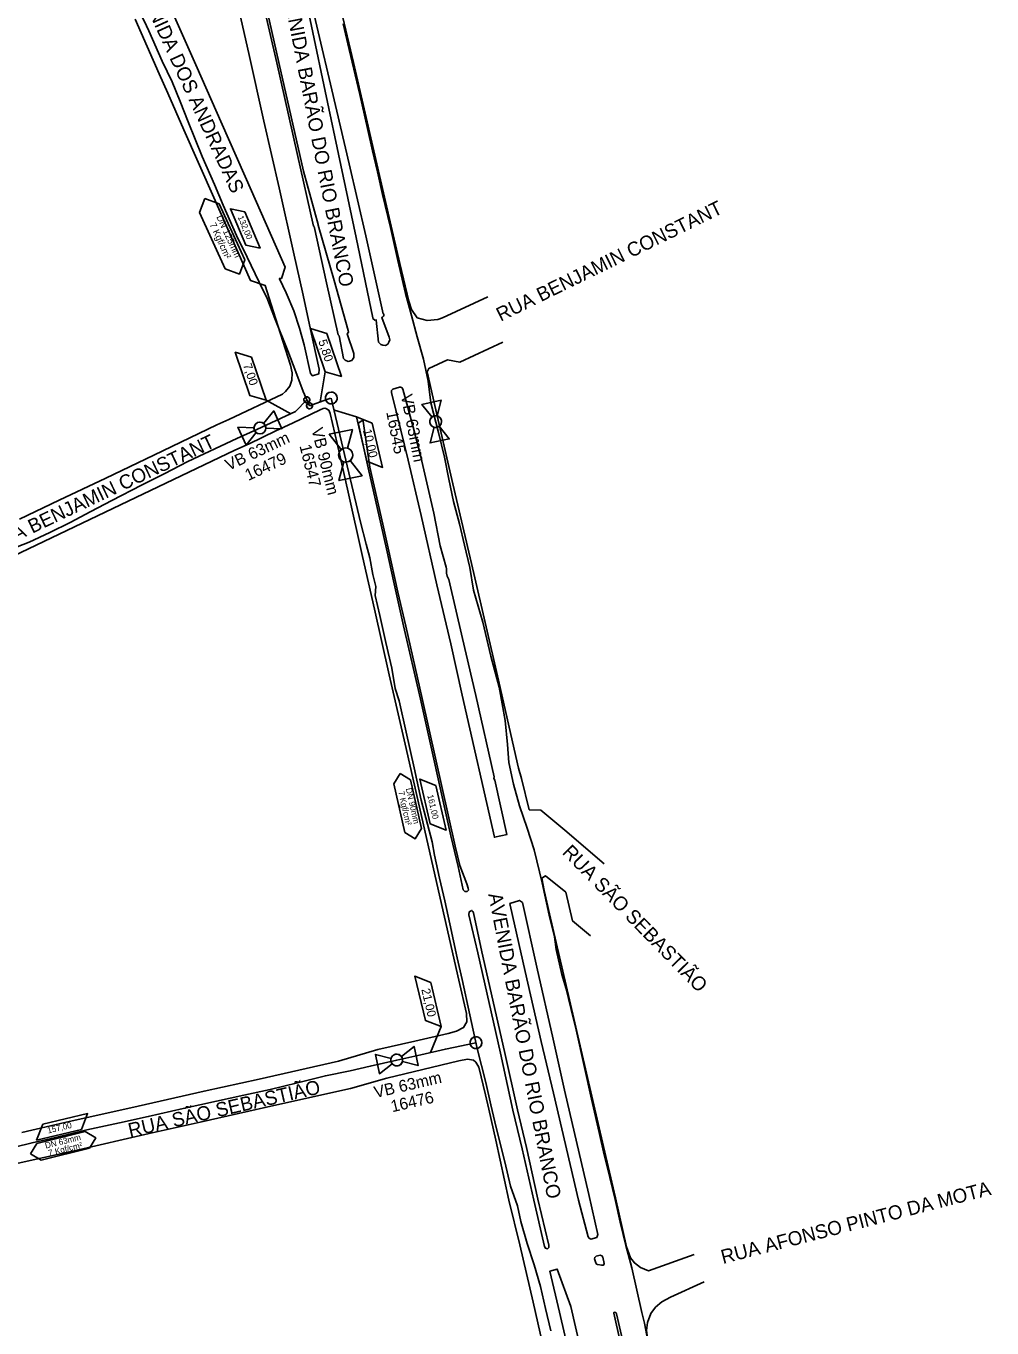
# Model space of a CAD drawing. Extents: x 656692 to 673945, y 7585994 to 7599066.
# Drawn here: x 669731 to 670226, y 7594792 to 7595459 of the extents above; entities that cross this region are included whole.
import ezdxf

# ---------------------------------------------------------------- set-up
doc = ezdxf.new("R2010")
doc.units = 0
for name, color, linetype in [('LOGRADOURO', 7, 'Continuous'), ('LOGRADOURO_TEXTO', 7, 'Continuous'), ('MEIO FIO', 7, 'Continuous'), ('SIMBOLO', 7, 'Continuous'), ('TEXTO', 7, 'Continuous'), ('TUBO_PEAD_GN_125', 7, 'Continuous'), ('TUBO_PEAD_GN_63', 7, 'Continuous'), ('TUBO_PEAD_GN_90', 7, 'Continuous'), ('VALVULA_PEAD_63', 7, 'Continuous'), ('VALVULA_PEAD_90', 7, 'Continuous')]:
    doc.layers.add(name, color=color, linetype=linetype)

# ---------------------------------------------------------------- blocks, each defined once
blk = doc.blocks.new('VALVULA_PEAD_DN_16')
at = {"layer": 'VALVULA_PEAD_63'}
for points in [[(-0.0374, 0.0187), (-0.1395, 0.0698), (-0.1395, -0.0698), (-0.0374, -0.0187)], [(-0.0374, -0.0187), (-0.1395, -0.0698), (-0.1395, 0.0698), (-0.0374, 0.0187)], [(0.0374, -0.0187), (0.1395, -0.0698), (0.1395, 0.0698), (0.0374, 0.0187)], [(0.0374, -0.0187), (0.1395, -0.0698), (0.1395, 0.0698), (0.0374, 0.0187)]]:
    blk.add_lwpolyline(points, dxfattribs=at)
blk.add_circle((0, 0), 0.0419, dxfattribs=at)
for start, end in [(90, 270), (153.43495, 206.56505), (270, 90), (333.43495, 26.56505)]:
    blk.add_arc((0, 0), 0.0419, start, end, dxfattribs=at)
blk = doc.blocks.new('INTERLIGACAO_9')
at = {"layer": 'SIMBOLO'}
blk.add_circle((0, 0), 4.19, dxfattribs=at)
for start, end in [(0, 180), (180, 0)]:
    blk.add_arc((0, 0), 4.19, start, end, dxfattribs=at)
blk = doc.blocks.new('VALVULA_PEAD_DN_17')
for points in [[(-0.0374, 0.0187), (-0.1395, 0.0698), (-0.1395, -0.0698), (-0.0374, -0.0187)], [(-0.0374, -0.0187), (-0.1395, -0.0698), (-0.1395, 0.0698), (-0.0374, 0.0187)], [(0.0374, -0.0187), (0.1395, -0.0698), (0.1395, 0.0698), (0.0374, 0.0187)], [(0.0374, -0.0187), (0.1395, -0.0698), (0.1395, 0.0698), (0.0374, 0.0187)]]:
    blk.add_lwpolyline(points)
blk.add_circle((0, 0), 0.0419)
for start, end in [(90, 270), (153.43495, 206.56505), (270, 90), (333.43495, 26.56505)]:
    blk.add_arc((0, 0), 0.0419, start, end)

msp = doc.modelspace()

# ---------------------------------------------------------------- linework, layer by layer
at = {"layer": 'LOGRADOURO'}
for points in [[(669907.78, 7595565.23), (669885.57, 7595555.02), (669882.73, 7595552.97), (669879.76, 7595549.96), (669876.58, 7595543.18), (669876.74, 7595537.65), (669880.81, 7595518.96), (669884, 7595505.49), (669890.56, 7595477.33), (669899.18, 7595440.34), (669919.49, 7595352.19), (669922.93, 7595337.43), (669927.48, 7595318.19), (669928.82, 7595313.85), (669931.88, 7595309.53), (669937, 7595308.26), (669942.3, 7595308.75), (669944.73, 7595309.52), (669968, 7595320.27)], [(669847.68, 7595493.52), (669859.85, 7595440.29), (669870.31, 7595393.79), (669878.66, 7595356.6), (669879.02, 7595356.35), (669885.28, 7595327.51), (669891.37, 7595300.95), (669891.81, 7595300.34), (669894.13, 7595288.83), (669894.93, 7595287.84), (669896.37, 7595287.28), (669898.32, 7595287.69), (669899.4, 7595289.2), (669899.29, 7595291.4), (669895.9, 7595301.41), (669896.62, 7595302.19), (669896.46, 7595303.07), (669889.34, 7595328.64), (669881.04, 7595356.99), (669881.13, 7595357.44), (669873.53, 7595384.69), (669860.86, 7595440.34), (669848.96, 7595493.48)], [(669874.02, 7595485.91), (669888.13, 7595426.35), (669896.89, 7595388.51), (669905.46, 7595351.58), (669914.41, 7595311.64), (669914.67, 7595311.71), (669914.75, 7595311.59), (669914.73, 7595310.84), (669914.47, 7595310.41), (669914, 7595309.87), (669913.69, 7595309.76), (669917.42, 7595299.72), (669917.73, 7595298.32), (669917.35, 7595297.05), (669916.69, 7595296.08), (669915.57, 7595295.48), (669914.25, 7595295.52), (669913.14, 7595295.97), (669911.95, 7595297.19), (669910.86, 7595308.45), (669910.77, 7595308.49), (669910.17, 7595308.45), (669909.17, 7595309.29), (669909.13, 7595309.57), (669900.55, 7595350.71), (669892.72, 7595387.8), (669884.68, 7595425.72), (669871.99, 7595485.94)], [(669803.34, 7595473.27), (669818.44, 7595439.25), (669832, 7595408.67), (669846.87, 7595374.72), (669864.18, 7595335.47), (669862.28, 7595329.75), (669862.19, 7595329.72), (669861.18, 7595329.67), (669861.26, 7595329.63), (669864.66, 7595322.41), (669868.66, 7595313.11), (669871.61, 7595304.38), (669873.86, 7595295.78), (669877.21, 7595281.13), (669878.24, 7595279.88), (669881.41, 7595280.9), (669881.64, 7595283.26), (669878.48, 7595297.33), (669873.12, 7595322.69), (669868.71, 7595341.65), (669861.05, 7595376.23), (669853.33, 7595410.35), (669845.58, 7595445.09), (669838.19, 7595477.44)], [(669787.41, 7595462.62), (669799.64, 7595434.65), (669804.01, 7595424.72), (669812.31, 7595405.97), (669827.73, 7595371.32), (669846.4, 7595328.72), (669853.89, 7595326.19), (669859.26, 7595309.49), (669866.88, 7595285.36), (669867.82, 7595281.5), (669867.55, 7595277.68), (669866.64, 7595274.59), (669864.44, 7595271.81), (669862.78, 7595270.56), (669835.34, 7595257.59), (669829.11, 7595254.72), (669796.87, 7595239.31), (669772.3, 7595227.42), (669748.41, 7595216.11), (669728.17, 7595206.43)], [(669975.6, 7595297.17), (669953.72, 7595286.93), (669947.3, 7595288.11), (669937.72, 7595283.64), (669936.89, 7595282), (669936.89, 7595281.9), (669942.98, 7595254.99), (669950.14, 7595224.52), (669960.8, 7595178.58), (669972.95, 7595126.26), (669983.77, 7595078.9), (669985.2, 7595073.62), (669989.19, 7595057.63), (669995.12, 7595057.44), (670007.36, 7595047.07), (670027.52, 7595029.85)], [(669729.3, 7594892.29), (669751.27, 7594897.29), (669788.86, 7594905.75), (669822.66, 7594913.51), (669850.87, 7594919.61), (669891.52, 7594928.79), (669911.64, 7594934.74), (669930.59, 7594939.03), (669947.69, 7594943.04), (669951.87, 7594944.08), (669955.55, 7594945.98), (669957.29, 7594948.91), (669956.99, 7594953.18), (669953.17, 7594970.37), (669945.84, 7595002.53), (669935.85, 7595046.14), (669926.24, 7595088.99), (669917.53, 7595126.77), (669910.01, 7595160.43), (669903.81, 7595187.34), (669896.39, 7595220.22), (669890.75, 7595245.28), (669887.26, 7595260.64), (669886.5, 7595262.29), (669885.04, 7595263.21), (669884.55, 7595263.36), (669883.63, 7595263.17), (669882.15, 7595262.52), (669867.9, 7595255.65), (669859.32, 7595251.64), (669845.7, 7595244.97), (669838.43, 7595241.73), (669654.33, 7595153.92)], [(670073.62, 7594829.74), (670050.37, 7594821.42), (670046.23, 7594823.01), (670043.09, 7594825.42), (670041.02, 7594827.99), (670039.06, 7594833.65), (670033.3, 7594858.86), (670027.19, 7594885.07), (670009.76, 7594960.24), (669999.64, 7595004.33), (669996.91, 7595016.3), (669995.63, 7595022.47), (669997.51, 7595023.7), (670007.97, 7595015.36)], [(670007.97, 7595015.36), (670011.36, 7595000.68), (670020.5, 7594993.02)], [(670009.62, 7594778.82), (670004.65, 7594800.2), (669999.77, 7594821.17), (670003.56, 7594822.27), (670010.54, 7594803.15), (670015.84, 7594779.99)], [(670078.86, 7594815.72), (670061.63, 7594807.82), (670057.06, 7594805.5), (670053.89, 7594802.78), (670051.56, 7594799.51), (670049.75, 7594794.84), (670049.27, 7594790.89), (670049.85, 7594786.85), (670054.48, 7594766.8), (670089.15, 7594616.81), (670129.02, 7594627.13)]]:
    msp.add_lwpolyline(points, dxfattribs=at)
for points in [[(669933.72, 7595238.39), (669940.38, 7595209.47), (669943.57, 7595192.8), (669946.66, 7595181.9), (669946.77, 7595180.96), (669946.87, 7595179.87), (669946.76, 7595178.72), (669947.22, 7595177.33), (669948.06, 7595175.5), (669955.08, 7595145.35), (669961.87, 7595116.19), (669971.27, 7595074.5), (669971.09, 7595073.6), (669971.51, 7595072.7), (669977.73, 7595044.96), (669977.83, 7595044.96), (669971.34, 7595043.54), (669971.44, 7595043.54), (669954.91, 7595116.22), (669948.97, 7595142.53), (669941.86, 7595172.76), (669933.77, 7595208.33), (669927.12, 7595236.73), (669923.41, 7595252), (669918.58, 7595271.41), (669918.69, 7595272.32), (669919.27, 7595273.02), (669922.78, 7595274), (669923.33, 7595274.09), (669923.94, 7595273.86), (669924.52, 7595273.13), (669929.68, 7595253.57)], [(669901.92, 7595255.89), (669903.6, 7595257.05), (669904, 7595257), (669904.21, 7595256.72), (669907.61, 7595233.05), (669914.25, 7595203.86), (669916.9, 7595191.64), (669921.97, 7595169.04), (669925.92, 7595151.63), (669934.31, 7595114.51), (669951.32, 7595039), (669953.65, 7595029.09), (669957.3, 7595019.71), (669957.99, 7595017.44), (669958.08, 7595016.39), (669957.35, 7595015.74), (669956.22, 7595015.7), (669955.42, 7595016.56), (669952.77, 7595028.56), (669949.12, 7595044.28), (669933.44, 7595114.16), (669924.86, 7595151.76), (669920.03, 7595173.36), (669916.08, 7595191.21), (669913.31, 7595203.39), (669906.66, 7595232.68), (669901.69, 7595255.2), (669901.59, 7595255.62)], [(669958.36, 7595005.34), (669958.26, 7595003.7), (669962.82, 7594984.29), (669974.41, 7594932.89), (669980.84, 7594903.75), (669985.54, 7594883.92), (669991.59, 7594857.56), (669997.01, 7594833.82), (669997.48, 7594832.96), (669998.51, 7594832.71), (669999.25, 7594833.36), (669999.21, 7594834.46), (669993.66, 7594858.08), (669987.83, 7594884.51), (669983.26, 7594903.9), (669976.48, 7594933.74), (669964.97, 7594984.87), (669960.71, 7595004.71), (669960.27, 7595005.54), (669959.82, 7595006.01)], [(669979.32, 7595009.64), (669979.4, 7595008.76), (669987.12, 7594974.66), (669995.38, 7594938.88), (670001.59, 7594912.33), (670014.47, 7594857.62), (670019.46, 7594838.79), (670019.91, 7594838.08), (670020.68, 7594837.69), (670023.75, 7594838.47), (670024.32, 7594840.05), (670019.71, 7594860.57), (670007.22, 7594913.86), (670001.46, 7594940.06), (669993.17, 7594976.87), (669985.73, 7595010.07), (669984.21, 7595011.18)], [(670023.52, 7594828.95), (670022.76, 7594828.23), (670022.63, 7594827.57), (670023.25, 7594825.5), (670023.62, 7594824.87), (670024.13, 7594824.61), (670026.36, 7594824.23), (670027.28, 7594824.37), (670027.61, 7594825.14), (670026.98, 7594828.36), (670026.45, 7594829.06), (670025.47, 7594829.36)], [(670032.65, 7594800.24), (670033.53, 7594800.1), (670033.87, 7594799.41), (670040.42, 7594771.17), (670058.47, 7594692.58), (670065.55, 7594662.9), (670068.13, 7594650.58), (670068.01, 7594649.64), (670067.16, 7594648.87), (670065.59, 7594648.65), (670064.86, 7594648.74), (670064.35, 7594649.8), (670063.84, 7594662.49), (670055.57, 7594698.95), (670046.47, 7594738.46), (670039.06, 7594770.75), (670032.48, 7594799.71)]]:
    msp.add_lwpolyline(points, close=True, dxfattribs=at)
at = {"layer": 'MEIO FIO'}
for p, q in [((669916.26, 7594920.13), (669953.11, 7594928.98)), ((669953.11, 7594928.98), (669957.58, 7594929.79)), ((669953.11, 7594928.98), (669953.11, 7594928.98)), ((669957.58, 7594929.79), (669960.59, 7594929.39)), ((669957.58, 7594929.79), (669957.58, 7594929.79)), ((669960.59, 7594929.39), (669961.83, 7594928.31)), ((669960.59, 7594929.39), (669960.59, 7594929.39)), ((669961.83, 7594928.31), (669963.38, 7594925.8)), ((669961.83, 7594928.31), (669961.83, 7594928.31)), ((669963.38, 7594925.8), (669966.84, 7594911.47)), ((669963.38, 7594925.8), (669963.38, 7594925.8)), ((669897.69, 7594914.84), (669916.26, 7594920.13)), ((669916.26, 7594920.13), (669916.26, 7594920.13)), ((669859.87, 7594906.42), (669897.69, 7594914.84)), ((669897.69, 7594914.84), (669897.69, 7594914.84)), ((669820.7, 7594897.55), (669859.87, 7594906.42)), ((669859.87, 7594906.42), (669859.87, 7594906.42)), ((669966.84, 7594911.47), (669968.53, 7594904.18)), ((669966.84, 7594911.47), (669966.84, 7594911.47)), ((669968.53, 7594904.18), (669972.14, 7594888.38)), ((669968.53, 7594904.18), (669968.53, 7594904.18)), ((669794.49, 7594891.66), (669820.7, 7594897.55)), ((669820.7, 7594897.55), (669820.7, 7594897.55)), ((669756.06, 7594882.89), (669794.49, 7594891.66)), ((669794.49, 7594891.66), (669794.49, 7594891.66)), ((669972.14, 7594888.38), (669978.82, 7594857.66)), ((669972.14, 7594888.38), (669972.14, 7594888.38)), ((669731.96, 7594877.52), (669756.06, 7594882.89)), ((669756.06, 7594882.89), (669756.06, 7594882.89)), ((669723.65, 7594875.61), (669731.96, 7594877.52)), ((669731.96, 7594877.52), (669731.96, 7594877.52)), ((669978.82, 7594857.66), (669984.35, 7594834.71)), ((669978.82, 7594857.66), (669978.82, 7594857.66)), ((669984.35, 7594834.71), (669991.2, 7594805.3)), ((669984.35, 7594834.71), (669984.35, 7594834.71)), ((669991.2, 7594805.3), (669997.16, 7594778.82)), ((669991.2, 7594805.3), (669991.2, 7594805.3))]:
    msp.add_line(p, q, dxfattribs=at)
at = {"layer": 'SIMBOLO'}
for points in [[(669823.04, 7595370.78), (669830.31, 7595368.08), (669843.47, 7595339.3), (669840.77, 7595332.03), (669833.5, 7595334.74), (669820.34, 7595363.52), (669823.04, 7595370.78)], [(669923.13, 7595076.18), (669928.43, 7595072.85), (669934.07, 7595047.94), (669930.74, 7595042.65), (669925.44, 7595045.99), (669919.8, 7595070.89), (669923.13, 7595076.18)], [(669733.79, 7594881.25), (669737.02, 7594886.6), (669761.81, 7594892.74), (669767.17, 7594889.51), (669763.93, 7594884.15), (669739.15, 7594878.02), (669733.79, 7594881.25)]]:
    msp.add_lwpolyline(points, dxfattribs=at)
at = {"layer": 'TEXTO'}
for p, q in [((669884.63, 7595281.96), (669882.08, 7595266.48)), ((669854.41, 7595267.47), (669867.12, 7595260.45)), ((669900.7, 7595258.88), (669889.4, 7595262.28)), ((669944.05, 7594946.5), (669938.62, 7594933.21))]:
    msp.add_line(p, q, dxfattribs=at)
for points in [[(669843.51, 7595363.89), (669851.31, 7595345.37), (669843.97, 7595346.86), (669836.12, 7595365.5), (669843.51, 7595363.89)], [(669885.56, 7595301.63), (669892.97, 7595279.61), (669884.63, 7595281.96), (669877.18, 7595304.11), (669885.56, 7595301.63)], [(669847.02, 7595289.44), (669854.43, 7595267.43), (669846.09, 7595269.78), (669838.64, 7595291.93), (669847.02, 7595289.44)], [(669847.02, 7595289.44), (669854.43, 7595267.43), (669846.1, 7595269.78), (669838.64, 7595291.93), (669847.02, 7595289.44)], [(669908.81, 7595255.62), (669914.11, 7595233), (669906.04, 7595236.13), (669900.7, 7595258.88), (669908.81, 7595255.62)], [(669941.34, 7595070.03), (669946.7, 7595047.14), (669938.53, 7595050.31), (669933.13, 7595073.33), (669941.34, 7595070.03)], [(669938.75, 7594969.11), (669944.05, 7594946.5), (669935.98, 7594949.63), (669930.64, 7594972.38), (669938.75, 7594969.11)], [(669938.75, 7594969.11), (669944.05, 7594946.5), (669935.98, 7594949.62), (669930.64, 7594972.38), (669938.75, 7594969.11)], [(669740.13, 7594896.55), (669763, 7594901.96), (669759.86, 7594893.79), (669736.84, 7594888.34), (669740.13, 7594896.55)], [(669740.13, 7594896.55), (669763, 7594901.97), (669759.86, 7594893.79), (669736.85, 7594888.34), (669740.13, 7594896.55)]]:
    msp.add_lwpolyline(points, dxfattribs=at)
at = {"layer": 'TUBO_PEAD_GN_125'}
msp.add_line((669887.47, 7595268.4), (669876.69, 7595264.55), dxfattribs=at)
msp.add_lwpolyline([(669772.18, 7595503.71), (669779.22, 7595488.18), (669784.3, 7595477.64), (669786.74, 7595472.07), (669792.04, 7595461.75), (669794.34, 7595456.68), (669801.22, 7595441.08), (669806.29, 7595430.51), (669810.45, 7595420.39), (669814.54, 7595410.08), (669821.65, 7595392.3), (669828.01, 7595377.85), (669832.38, 7595367.25), (669839.26, 7595351.8), (669844.71, 7595340.75), (669852.94, 7595323.62), (669854.78, 7595319.98), (669858.93, 7595309.26), (669865.49, 7595292.74), (669869.6, 7595281.87), (669873.37, 7595271.9), (669876.69, 7595264.55)], dxfattribs=at)
at = {"layer": 'TUBO_PEAD_GN_63'}
for points in [[(669893.91, 7595460.26), (669896.29, 7595449.98), (669898.49, 7595440.62), (669902.38, 7595424.07), (669906.4, 7595406.66), (669908.98, 7595395.07), (669911.46, 7595384.39), (669914.1, 7595372.85), (669918.06, 7595355.89), (669921.92, 7595339), (669925.9, 7595322.07), (669928.85, 7595310.84), (669931.88, 7595299.8), (669935.05, 7595288.36), (669937.37, 7595277.18), (669938.72, 7595265.99), (669942.74, 7595250.85), (669945.83, 7595238.16), (669948.1, 7595226.94), (669950.4, 7595215.45), (669953.51, 7595204.14), (669956.06, 7595193.11), (669958.8, 7595181.77), (669960.6, 7595170.04), (669965.42, 7595153.65), (669969.48, 7595136.31), (669973.72, 7595120.33), (669976.86, 7595103.31), (669978.14, 7595091.07), (669978.79, 7595081.78), (669981.09, 7595070.62), (669984.17, 7595059.54), (669988.21, 7595048.09), (669991.64, 7595037.09), (669995.8, 7595020.1), (669999.42, 7595003.58), (670002.1, 7594992.41), (670003.05, 7594985.92), (670005.96, 7594973.2), (670008.1, 7594965.89), (670011.92, 7594950.26), (670013.25, 7594944.8), (670017.21, 7594927.08), (670021.16, 7594909.32), (670024.99, 7594892.3), (670027.62, 7594880.86), (670030.43, 7594869.23), (670033.18, 7594857.86), (670035.71, 7594846.23), (670038.61, 7594834.33), (670041.67, 7594822.93), (670044.27, 7594811.56), (670046.81, 7594800.06), (670048.31, 7594794.53), (670050.44, 7594782.77)], [(669651.19, 7595156.38), (669652.77, 7595157.35), (669662.73, 7595163.12), (669673.73, 7595168.87), (669684.25, 7595174.12), (669694.82, 7595178.96), (669705.67, 7595183.31), (669715.82, 7595188.05), (669733.03, 7595194.66), (669743.71, 7595199.55), (669754.07, 7595204.78), (669764.71, 7595210.45), (669775.42, 7595215.98), (669790.56, 7595223.91), (669802.13, 7595229.73), (669814.3, 7595236.08), (669839.51, 7595247.78), (669849.68, 7595252.43), (669869.56, 7595261.57), (669875.3, 7595267.62)], [(669715.23, 7594883.17), (669717.75, 7594884.68), (669725.53, 7594884.79), (669734.55, 7594887.01), (669742.89, 7594888.83), (669753.52, 7594891.42), (669762.6, 7594893.55), (669779.39, 7594897.23), (669794.07, 7594900.43), (669811.9, 7594904.5), (669829.06, 7594908.31), (669843.07, 7594911.41), (669856.57, 7594914.29), (669870.57, 7594917.76), (669884.79, 7594921.32), (669897.47, 7594923.92), (669907.73, 7594926.18), (669921.38, 7594929.39), (669933.64, 7594932.07), (669946.24, 7594934.98), (669961.89, 7594938.24)]]:
    msp.add_lwpolyline(points, dxfattribs=at)
at = {"layer": 'TUBO_PEAD_GN_90'}
msp.add_lwpolyline([(669887.8, 7595268.52), (669902.85, 7595204.85), (669905.62, 7595193.6), (669907.56, 7595186.59), (669909.08, 7595178.19), (669910.54, 7595171.99), (669910.33, 7595167.42), (669912.72, 7595157.08), (669915.72, 7595143.27), (669918.75, 7595130.16), (669920.57, 7595119.7), (669922.54, 7595113.43), (669926.11, 7595097.38), (669930.2, 7595079.04), (669933.9, 7595062.49), (669939.45, 7595041.2), (669940.7, 7595034.38), (669943.18, 7595022.57), (669945.93, 7595010.96), (669948.45, 7594999.16), (669952.37, 7594981.66), (669954.81, 7594970.61), (669958.72, 7594952.6), (669962.54, 7594935.27), (669967.02, 7594917.87), (669969.6, 7594906.41), (669972.33, 7594894.79), (669976.69, 7594877.28), (669979.58, 7594864.68), (669983.19, 7594854.63), (669984.87, 7594846.61), (669988.17, 7594835.43), (669991.8, 7594824.45), (669994.95, 7594813.41), (669997.59, 7594802.1), (670000.25, 7594790.64)], dxfattribs=at)

# ---------------------------------------------------------------- block references
at = {"layer": 'SIMBOLO', "rotation": 166.312122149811}
for p, xscale, yscale in [((669887.8, 7595268.52), 0.7229249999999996, 0.7229249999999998), ((669875.28, 7595267.6), 0.3614624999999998, 0.3614624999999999), ((669876.66, 7595264.52), 0.3614624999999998, 0.3614624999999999), ((669961.89, 7594938.24), 0.7229249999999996, 0.7229249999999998)]:
    msp.add_blockref('INTERLIGACAO_9', p, dxfattribs=dict(at, xscale=xscale, yscale=yscale))
at = {"layer": 'VALVULA_PEAD_63'}
for p, xscale, yscale, rotation in [((669941.26, 7595256.44), 72.29249999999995, 72.29249999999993, -78.18143432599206), ((669851.25, 7595253.15), 72.29249999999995, 72.29249999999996, 24.566402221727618), ((669921.34, 7594929.38), 72.2924999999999, 72.29249999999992, 11.818565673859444), ((669921.34, 7594929.38), 72.2924999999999, 72.29249999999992, 11.818565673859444), ((669921.34, 7594929.38), 72.2924999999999, 72.29249999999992, 11.818565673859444)]:
    msp.add_blockref('VALVULA_PEAD_DN_16', p, dxfattribs=dict(at, xscale=xscale, yscale=yscale, rotation=rotation))
at = {"layer": 'VALVULA_PEAD_90', "xscale": 86.75099999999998, "yscale": 86.75099999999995, "rotation": -78.25260528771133}
msp.add_blockref('VALVULA_PEAD_DN_17', (669895.19, 7595239.3), dxfattribs=at)

# ---------------------------------------------------------------- texts
for s, rotation, p in [('VB 63mm', 281.04801, (669923.41, 7595269.85)), ('16545', 281.04801, (669915.92, 7595261.32)), ('VB 90mm', 284.09848, (669877.57, 7595252.5)), ('VB 63mm', 25.04801, (669835.21, 7595231.17)), ('16479', 25.04801, (669845.3, 7595225.97)), ('16547', 284.09848, (669871.46, 7595244.01)), ('VB 63mm', 13.04801, (669910.48, 7594909.85)), ('16476', 13.04801, (669919.04, 7594902.6))]:
    msp.add_text(s, height=6, rotation=rotation).set_placement(p)
at = {"layer": 'LOGRADOURO_TEXTO'}
for s, rotation, p in [('AVENIDA DOS ANDRADAS', 294.63296, (669786.08, 7595483.65)), ('AVENIDA BARÃO DO RIO BRANCO', 280.99349, (669861.99, 7595481.46)), ('RUA BENJAMIN CONSTANT', 26.05221, (669974.54, 7595307.55)), ('RUA BENJAMIN CONSTANT', 25.36438, (669713.85, 7595189.13)), ('RUA SÃO SEBASTIÃO', 314.39127, (670005.68, 7595035.38)), ('AVENIDA BARÃO DO RIO BRANCO', 280.99349, (669968.17, 7595014.31)), ('RUA SÃO SEBASTIÃO', 12.95403, (669784.68, 7594889.75)), ('RUA AFONSO PINTO DA MOTA', 14.4566, (670088.44, 7594824.89))]:
    msp.add_text(s, height=7.2, rotation=rotation, dxfattribs=at).set_placement(p)
at = {"layer": 'TEXTO'}
for s, height, rotation, p in [('7 Kgf/cm²', 3.459, 294.57428, (669825.37, 7595357.4)), ('DN 125mm', 3.459, 294.57428, (669828.86, 7595361.29)), ('132,00', 3.113, 292.84821, (669839.8, 7595361.18)), ('5,80', 4.447, 288.6074, (669881.07, 7595297.65)), ('7,00', 4.447, 288.6074, (669842.53, 7595285.46)), ('10,00', 4.447, 283.19761, (669903.96, 7595252.08)), ('7 Kgf/cm²', 3.113, 282.77499, (669922.06, 7595066.78)), ('DN 90mm', 3.113, 282.77499, (669925.93, 7595068.4)), ('161,00', 3.113, 283.19761, (669936.96, 7595064.94)), ('21,00', 4.447, 283.19759, (669933.9, 7594965.57)), ('157,00', 3.113, 13.32841, (669742.75, 7594891.71)), ('DN 63mm', 3.113, 13.89932, (669741.59, 7594883.97)), ('7 Kgf/cm²', 3.113, 13.89932, (669743.28, 7594880.14))]:
    msp.add_text(s, height=height, rotation=rotation, dxfattribs=at).set_placement(p)

doc.saveas('drawing.dxf')
